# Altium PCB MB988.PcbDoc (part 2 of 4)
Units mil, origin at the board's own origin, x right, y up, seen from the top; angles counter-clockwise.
Board outline 4505 x 6805 mil, 4 copper layers (TopLayer, VCC, GND, BottomLayer), stack 71.6 mil thick; 546 components, 390 nets, 1907 pads, 809 vias.
Unrouted connection lines stored in the file: 2.
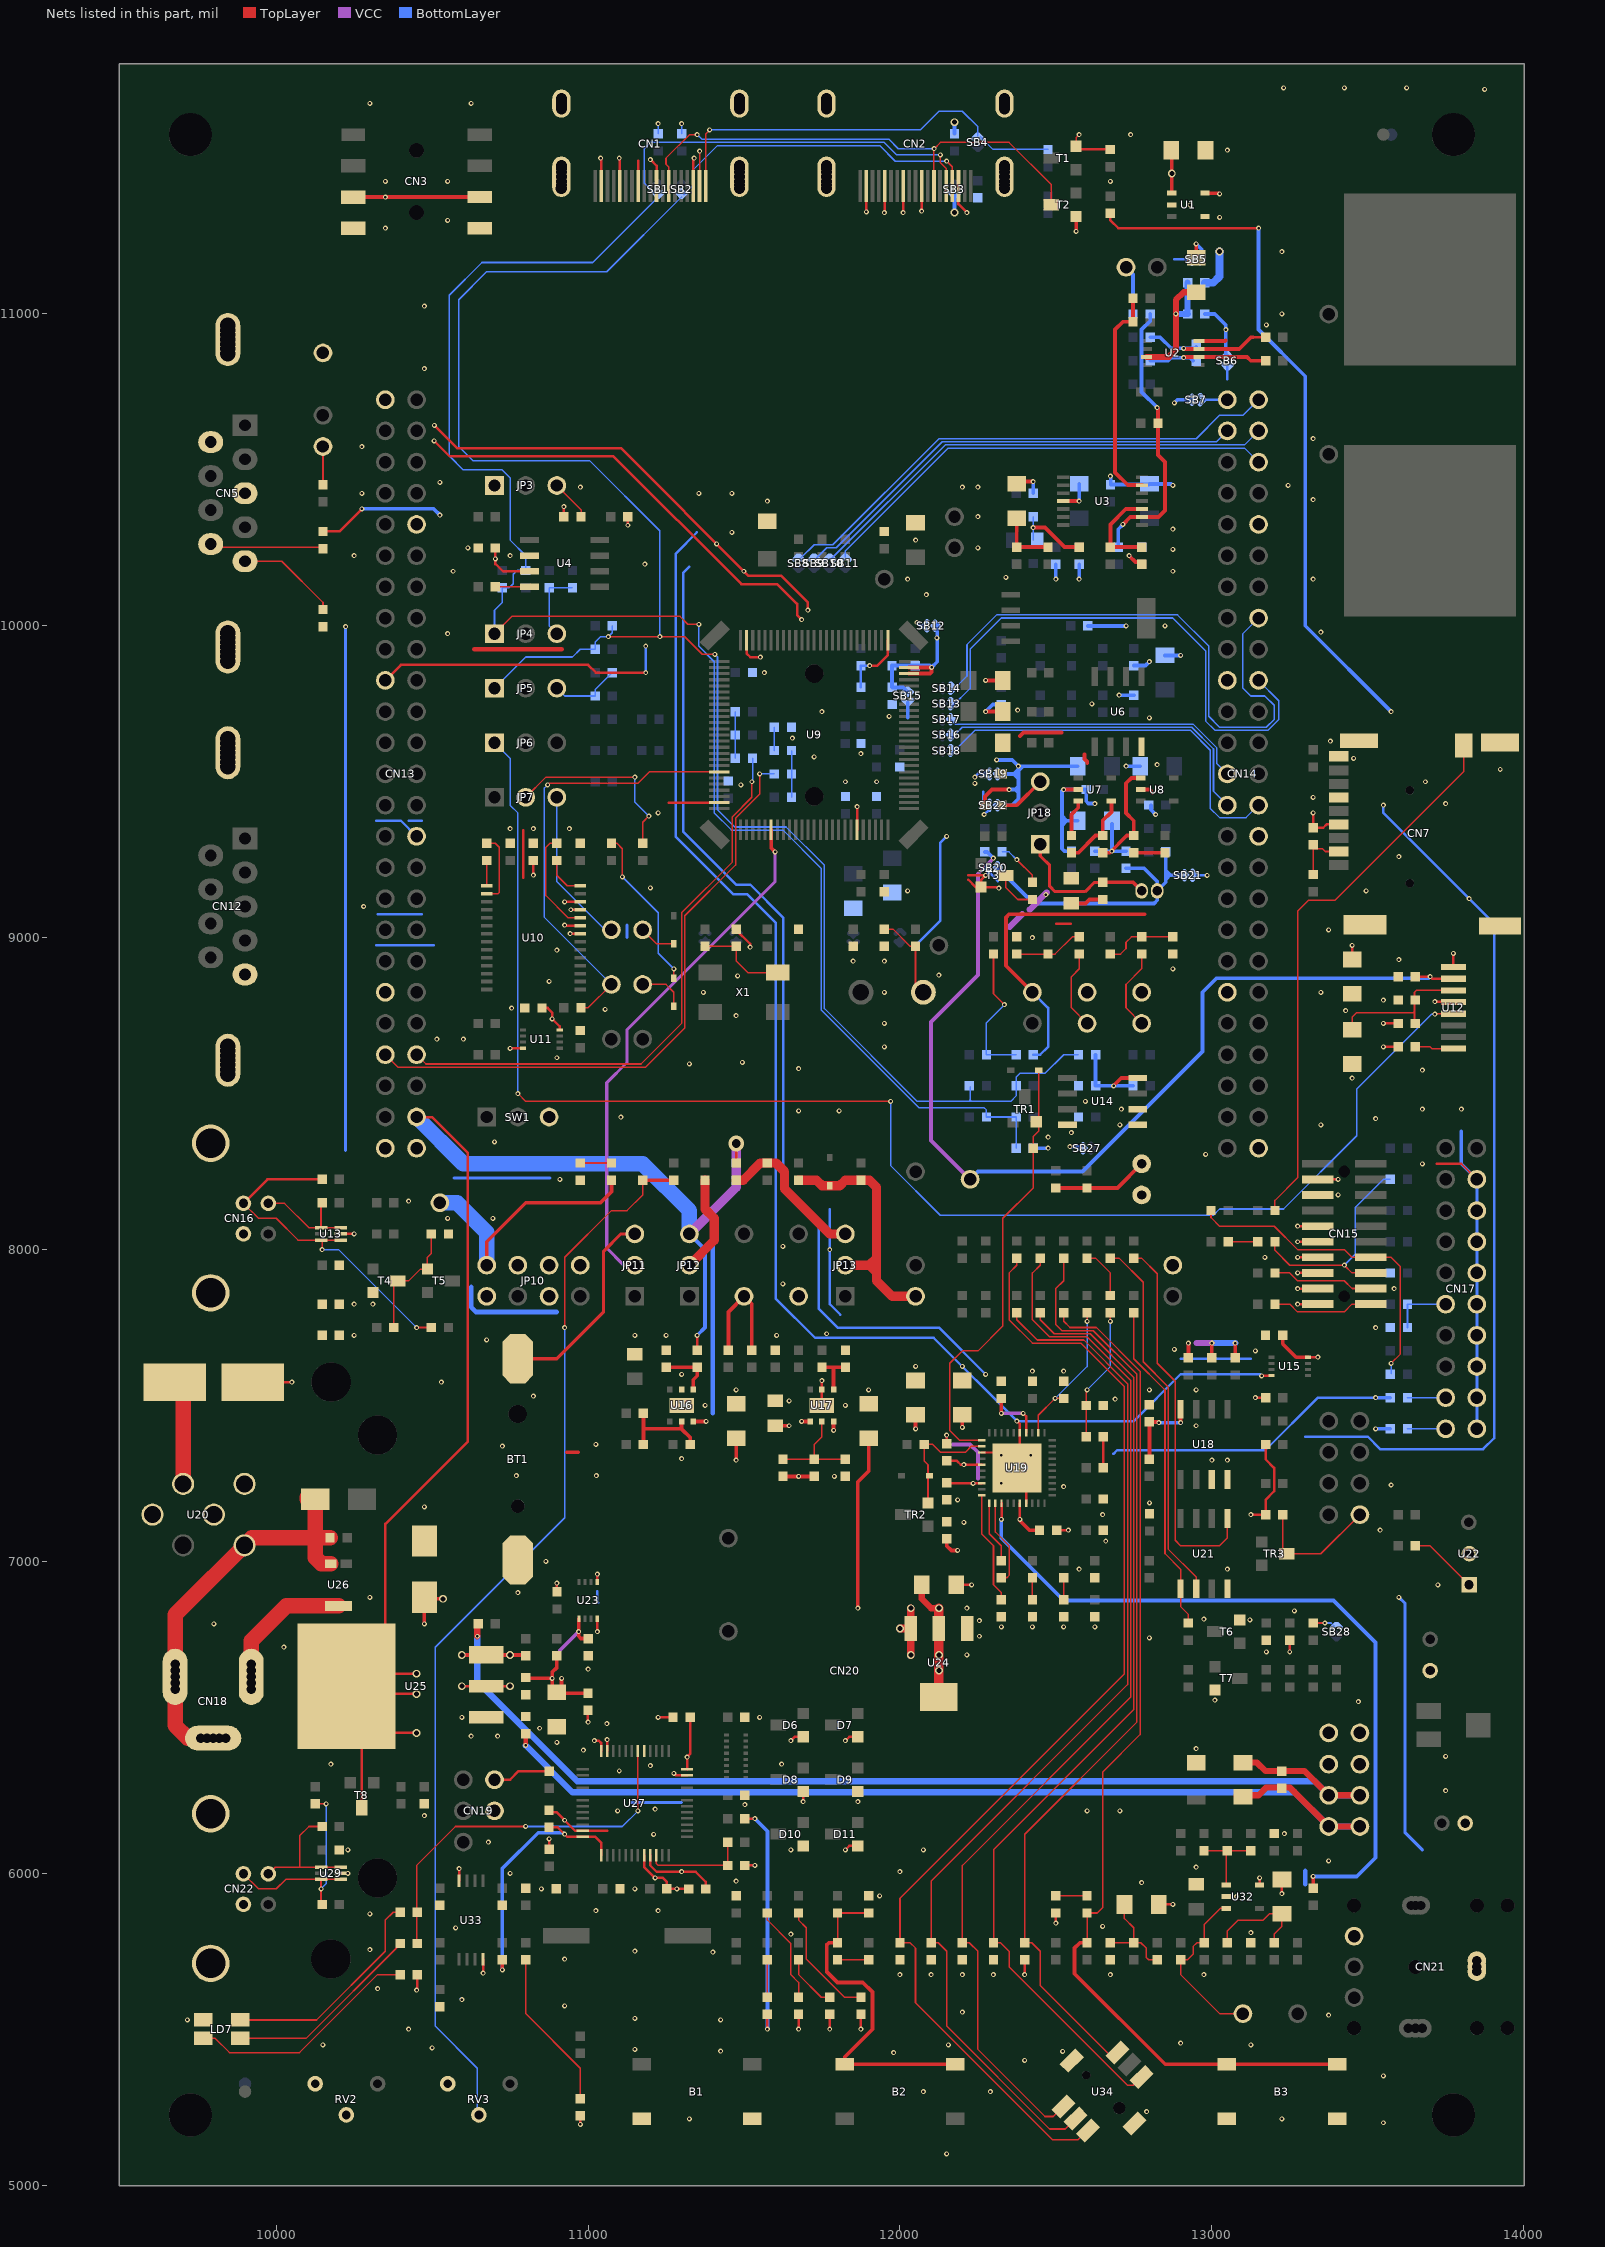
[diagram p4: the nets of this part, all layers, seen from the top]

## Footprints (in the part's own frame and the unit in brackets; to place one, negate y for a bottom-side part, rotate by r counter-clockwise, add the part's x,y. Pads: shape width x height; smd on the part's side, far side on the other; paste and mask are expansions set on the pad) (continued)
XTAL_socket [mil]
  round 80 hole 53 mask+4: 1(100,0) 2(-100,0)
  silkscreen extent -215,-89 214,89

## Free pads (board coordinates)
  round 137.8 hole 137.8 unplated mask+4: 0(9725,5225) 0(13775,5225) 0(13775,11575)
  round 137.79 hole 137.79 unplated mask+4: 0(9725,11575)

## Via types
v1: diameter 16, hole 8, TopLayer to BottomLayer, tented both sides, 786 vias
v2: diameter 25, hole 16, TopLayer to BottomLayer, tented both sides, 20 vias
v3: diameter 50, hole 28, TopLayer to BottomLayer, tented both sides, 3 vias

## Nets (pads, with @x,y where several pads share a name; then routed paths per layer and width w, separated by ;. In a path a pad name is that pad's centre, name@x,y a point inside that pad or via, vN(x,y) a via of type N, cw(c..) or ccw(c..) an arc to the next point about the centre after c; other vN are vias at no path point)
+1V8: C37.1 C41.2 R99.2 R102.2 R114.1 TP12.1 U17.4 | length 548.7
  TopLayer w12: R102.2@11450,7677.5 11450,7800 TP12.1@11500,7850 11525,7825 R99.2@11525,7677.5 ; C37.1@11600,7435 v1(11645,7435) ; C41.2@11625,7272.5 R114.1@11725,7272.5 ; v1(11685,7448.82) U17.4@11712.6,7448.82
  other v1: 11675,7272.5
+2V5: C32.1 C43.1 C49.1 C130.1 C132.1 R166.1 TP13.1 U19.13 U19.16 U19.34 U24.2 | length 3218.7
  TopLayer w8: v1@12325.79,7135.79 U19.13@12325.79,7187.01 ; v1@12384.84,7130.16 U19.16@12384.84,7187.01 ; v1(12395,7475) 12404.53,7465.47 U19.34@12404.53,7412.99
  TopLayer w12: C132.1@12150.28,7072.56 12150.28,7049.72 12165,7035 v1(12185,7035) ; v1(12200,7430) C32.1@12200,7470 ; v1@12325.28,7475.28 C43.1@12325.28,7522.44 ; v1@12384.84,7130.16 12415.28,7099.72 C130.1@12447.56,7099.72 ; R166.1@13325,5952.5 v1(13325,5990)
  TopLayer w20: C49.1@12070,6925 12070,6880 12100,6850 v2(12125,6850)
  TopLayer w30: U24.2@12125,6565 v2(12125,6850)
  VCC w12: v1(12325,7475) v1(12395,7475)
  BottomLayer w12: v1(12325,7135) 12325,7075 12525,6875 13390,6875 13525,6740 13525,6050 13465,5990 v1(13325,5990)
  other v1: 12384.84,7135
  other v2: 12125,6650 12125,6700
+3V3: C6.2 C12.2 C22.1 C23.1 C57.1 C58.1 C60.1 C61.2 C69.2 C76.2 C120.2 C124.2 C133.2 CN7.4 CN13.48 CN19.4 CN20.9 CN20.10 JP12.3 LD1.1 LD2.1 LD3.1 LD4.1 LD6.1 LD10.1 R2.2 R8.2 R9.1 R28.2 R48.1 R49.1 R56.2 R97.2 R110.2 R112.2 R118.2 R133.2 R153.2 R206.1 R237.1 R244.2 T8.3 TP7.1 U4.3 U10.22 U10.26 U11.8 U12.7 U15.8 U23.1 U25.2 U27.1 U27.9 U27.24 U27.36 U27.48 U32.5 U33.8 | length 14599.1
  TopLayer w8: R9.1@10150,10302.5 10202.5,10302.5 v1(10275,10375) ; T8.3@10274.5,6210 U25.2@10274.5,6509.5 ; U25.2@10300,6640 v2@10445,6640 ; U25.2@10305,6450 v2(10450,6450) ; U25.2@10305,6575 v2(10450,6575) ; U25.2@10350,6725 10350,7120 10615,7385 10615,8310 10500,8425 CN13.48@10450,8425 ; v1@10452.5,5627.5 R153.2@10452.5,5675 ; U33.8@10586.61,5975.98 v1(10586.61,6015) ; v2(10595,6600) v2(10750,6600) ; 10702.44,10197.56 C6.2@10702.44,10249.72 ; 10702.44,10200 10727.44,10175 U4.3@10812.5,10175 ; v1(10824.72,9200.28) C12.2@10824.72,9247.56 ; C120.2@10852.44,8774.72 10870.28,8774.72 10885,8760 v1(10885,8740) 10909.06,8715.94 U11.8@10909.06,8704.53 ; C69.2@10874.72,6147.56 10902.44,6147.56 10933.27,6116.73 11023.27,6116.73 11041.73,6098.27 U27.1@11041.73,6057.68 ; R8.2@10922.5,10350 v1(10922.5,10382.5) ; v1(10925,9115) 10925.16,9115.16 U10.26@10974.61,9115.16 ; v1(10942.8,9012.8) U10.22@10974.61,9012.8 ; v1(10975,5195) LD6.1@10975,5222.5 ; v1(11020,6425) 11035,6425 11041.73,6418.27 U27.36@11041.73,6392.32 ; U27.9@11199.21,6057.68 11199.21,6025.79 11220,6005 11345,6005 11377.44,5972.56 C76.2@11377.44,5949.72 ; U27.24@11317.32,6333.27 v1(11317.32,6372.68) 11327.44,6382.79 C61.2@11327.44,6499.72 ; R97.2@11350,7677.5 v1(11350,7725) ; R56.2@11475,8277.5 v3(11475,8340) ; R133.2@11502.5,6175 v1(11535,6175) ; v1(11575,5500) LD4.1@11575,5547.5 ; v1(11675,5500) LD3.1@11675,5547.5 ; v1(11775,5500) LD2.1@11775,5547.5 ; v1(11875,5500) LD1.1@11875,5547.5 ; R2.2@12675,11322.5 12675,11300 12700,11275 v1(13150,11275) ; v1(13125,7150) R112.2@13172.5,7150 13172.5,7197.5 13200,7225 13200,7300 13172.5,7327.5 R110.2@13172.5,7375 ; U32.5@13153.15,5962.4 v1(13153.15,5985) ; v1(13250,6710) R118.2@13250,6747.5 ; U15.8@13309.06,7654.53 13339.53,7654.53 v1(13340,7655) ; v1(13325,9400) R28.2@13325,9352.5 13357.5,9352.5 13367.99,9362.99 CN7.4@13406.65,9362.99 ; C22.1@13450,8930 v1(13450,8975) ; v1(13550,8650) R48.1@13597.5,8650 ; v1(13550,8725) R49.1@13597.5,8725 ; C23.1@13652.56,8875.28 13699.72,8875.28 13706.5,8868.5 U12.7@13775,8868.5
  TopLayer w12: v1(10725,5690) R244.2@10725,5722.5 ; C57.1@10802.28,6625 v1(10885,6625) ; C58.1@10885,6570 10885,6645 10900,6660 R237.1@10900,6697.5 ; C58.1@10912.56,6577.56 C60.1@10999.72,6577.56 ; C58.1@10915,6585 v1(10915,6625) ; U23.1@10970.47,6815.94 10970,6815.47 10970,6760 10977.56,6752.44 C133.2@11000.28,6752.44 ; C124.2@13227.44,7724.72 13227.44,7697.56 13270.47,7654.53 U15.8@13309.06,7654.53
  VCC w12: 10910,6715 v1(10970,6775) ; TP7.1@12225,8225 12100,8350 12100,8730 12250,8880 12250,9205 v1(12300,9255)
  VCC w30: JP12.3@11325,8050 11475,8200 v3(11475,8340)
  BottomLayer w12: v1(10275,10375) 10505,10375 v1(10525,10355) ; v1(10725,5690) 10725,6015 10840,6130 10920,6130 v1(10924.58,6125.42) ; JP12.3@11325,8050 11375,8000 11375,7750 v1(11350,7725) ; v1(11535,6175) 11575,6135 v1(11575,5500) ; TP7.1@12225,8225 12250,8250 12585,8250 12970,8635 12970,8825 13015,8870 13695,8870 v1(13700,8875) ; R206.1@12272.5,9275 12280,9275 v1(12300,9255) ; v1(13150,11275) 13150,10950 13300,10800 13300,10000 v1(13575,9725)
  BottomLayer w50: CN13.48@10450,8425 10600,8275 11175,8275 11325,8125 JP12.3@11325,8050
  other v1: 10450,5625 11300,6005 10985,6395 10702.44,10215
  other v2: 10450,6640
+5V: C39.1 C40.1 C42.1 C48.1 C121.2 C126.1 C127.2 C128.1 CN3.3 JP10.2 JP10.4 JP10.6 JP10.8 L2.2 R53.2 R101.1 R104.2 R105.2 R213.2 R214.2 R221.2 R235.1 R238.1 SB27.2 T2.2 TP8.1 U1.5 U14.8 U16.6 U17.6 U18.8 U19.5 U19.8 U24.3 U25.3 | length 4112.6
  TopLayer w8: C128.1@12149.72,7252.44 12151.37,7250.79 U19.8@12262.01,7250.79 ; C126.1@12150.28,7322.56 12182.44,7322.56 12195,7310 12235,7310 12235.16,7309.84 U19.5@12262.01,7309.84
  TopLayer w12: CN3.3@10247.5,11375 CN3.3@10652.5,11375 ; v1(10475,6800) C48.1@10475,6885 ; C48.1@10480,6880 v2(10535,6880) ; v2(10595,6700) U25.3@10655,6700 ; JP10.2@10675,7950 10675,8025 10800,8150 11040,8150 11075,8185 R53.2@11075,8222.5 ; U25.3@10700,6700 R238.1@10797.5,6700 ; U16.6@11337.4,7448.82 v1(11378.82,7448.82) ; v1(11475,7325) C40.1@11475,7395 ; v1(11787.4,7420) U17.6@11787.4,7448.82 ; v1(11865,6850) 11865,7254.95 11900,7289.95 C42.1@11900,7395 ; v1(12050,7425) C39.1@12050,7470 ; v1(12565,11265) T2.2@12565,11312.5 ; v1(12685,8525) 12710,8550 U14.8@12762.5,8550 ; R235.1@12800,7327.5 12800,7447.28 12827.72,7447.28 v1(12830,7445) ; v1(12900,7445) U18.8@12900,7487.5 ; R101.1@12925,7652.5 v1(12925,7700) ; U1.5@12978.15,11387.4 13022.6,11387.4 v1(13025,11385) ; R104.2@13000,7652.5 v1(13000,7700) ; R105.2@13075,7652.5 v1(13075,7700)
  TopLayer w25: v2(12000,6785) U24.3@12034.45,6785 ; v2(12035,6700) 12034.45,6700.55 12034.45,6849.45 v2(12035,6850)
  VCC w12: 12170,7375 12225,7375 12250,7350 12250,7265
  VCC w20: 12952,7700 v1(13000,7700)
  BottomLayer w12: R221.2@12425,8325 v1(12475,8325) ; v1(12545,8330) SB27.2@12582,8330 ; R213.2@12627.44,8624.94 C121.2@12627.44,8525.28 12627.72,8525 R214.2@12747.5,8525 ; v1(12830,7445) v1(12900,7445) ; 13025,11152.5 v2(13025,11200)
  BottomLayer w20: v1(13000,7700) v1(13075,7700)
  BottomLayer w25: L2.2@12977.5,11100 13005,11100 13025,11120 v2(13025,11200)
  BottomLayer w50: TP8.1@10525,8150 10580,8150 10675,8055 JP10.2@10675,7950
  other v1: 12235,7250 12205,7310 10350,11375
  other v2: 10750,6700
AGND: C3.2 C4.1 C5.2 C8.2 C9.2 C10.2 C11.2 C17.1 C90.1 C92.1 C93.1 C94.2 C95.2 C97.1 C100.1 C102.1 C103.1 C105.1 C106.2 C107.1 C108.2 C109.2 C111.1 C113.1 C114.2 C118.1 CN6.2 CN9.1 L3.2 R15.1 R30.1 R121.2 R188.1 R197.1 R198.2 R207.2 R208.1 SB5.2 SB6.2 SB7.2 SB12.2 SB15.2 SB19.2 SB20.2 SB21.2 SB22.2 U2.4 U3.11 U6.4 U7.2 U8.2 U9.48 U9.49 | length 5627.2
  TopLayer w8: CN6.2@12825,9150 CN6.2@12825,9171.5
  TopLayer w12: U9.48@12029.13,9846.85 12096.85,9846.85 12101.53,9851.53 v1(12101.53,9866.53) U9.49@12029.13,9866.53 ; R121.2@12272.5,9425 12272.5,9452.5 12295,9475 v1(12350,9475) ; v1(12275,9725) C10.2@12330,9725 ; v1(12275,9825) C9.2@12330,9825 ; 12350,9075 12340,9065 12340,8910 CN9.1@12425,8825 ; 12354,9075 12784,9075 ; 12385,9646.5 12396.5,9658 12518.69,9658 ; C5.2@12387.5,10462.5 v1(12427.5,10462.5) ; U3.11@12524.02,10400 v1(12575,10400) ; v1(12525,9475) U7.2@12571.85,9475 ; 12591.96,9588.34 12591.96,9573.04 12600.35,9564.65 12600.35,9560 ; v1(12735,10225) 12755,10205 R15.1@12775,10205 ; U8.2@12771.85,9475 12800,9475 12810,9465 ; C3.2@12950,11180 v1(12950,11225) ; U2.4@12959.69,10913.39 13043.39,10913.39 13045,10915
  VCC w20: 12352,9035 12392,9075 ; 12416,9090 v1@12471,9145
  BottomLayer w8: CN9.1@12425,8825 12475,8775 12475,8650 12450,8625 C118.1@12427.5,8625
  BottomLayer w12: L3.2@11974.72,9802.78 C102.1@11974.72,9872.44 12095.63,9872.44 v1(12101.53,9866.53) 12120,9885 SB12.2@12120,10005 ; L3.2@11975,9802.5 12010.5,9802.5 SB15.2@12025,9788 ; v1(12275,9725) 12297.5,9747.5 R197.1@12325,9747.5 ; v1(12310,9570) 12360,9570 v1(12380,9550) ; SB20.2@12313,9225 12428,9110 12815,9110 12825,9120 12825,9180 12782.56,9222.44 C113.1@12724.72,9222.44 ; SB19.2@12313,9525 12376.5,9525 ; SB22.2@12318,9425 12360,9425 12380,9445 v1(12380,9550) ; v1(12350,9475) 12380,9475 ; 12380,9465 12370,9475 12380,9485 ; 12380,9510 12365,9525 12380,9540 ; 12380,9535 12395,9550 ; C92.1@12427.5,10425 v1(12427.5,10462.5) ; v1(12500,10150) R188.1@12500,10197.5 ; 12520,9360 12535,9375 12520,9390 ; 12520,9375 C114.2@12570,9375 ; R207.2@12550,9277.5 12527.5,9277.5 12520,9285 12520,9470 v1(12525,9475) C107.1@12597.15,9475 ; C108.2@12570,9550 v1(12380,9550) ; C97.1@12574.72,10197.44 12574.72,10150.28 v1(12575,10150) ; v1(12575,10400) C94.2@12575,10455 ; C107.1@12597.44,9475.28 12597.44,9437.56 12605,9430 v1(12625,9430) ; C100.1@12602.56,9999.72 12724.72,9999.72 v1(12725,10000) ; v1(12675,10480) 12675.87,10479.13 12675.87,10453.15 C95.2@12798.15,10453.15 ; v1(12702.56,9777.56) C105.1@12750.28,9777.56 ; v1(12725,9550) C109.2@12770,9550 ; R198.2@12750,9872.5 12787.5,9872.5 v1(12800,9885) ; C95.2@12800,10455 12870,10455 v1(12875,10450) ; C111.1@12805,9425 12805,9410 v1(12820,9395) ; CN6.2@12825,9150 12852.5,9177.5 R208.1@12852.5,9275 ; C106.2@12850,9905 v1(12900,9905) ; 12852.5,9190 12855,9190 12865,9200 12865,9202.5 12852.5,9215 ; 12852.5,9200 SB21.2@12907,9200 ; v1(12880,10715) 12890,10725 SB7.2@12937,10725 ; v1(12950,11225) 12968,11207 SB5.2@12968,11182 ; C90.1@12977.56,10999.72 13009.72,10999.72 13045,10964.43 SB6.2@13045,10868 ; SB6.2@13050,10863 SB6.2@13050,10868
  other v1: 12467.79,9138.32 12825,9555 12800,9705 12377.5,9730 12615.31,9750 12118.17,9961.35 13350,9980 12850,10000 12085,10100 12025,10150 13325,10150 12340,10155 12875,10175 12875,10245 12250,10250 12050,10275 12875,10310 12250,10350 13325,10405 12200,10445 12250,10445 13325,10600 13045,10950 13175,10965 13225,11200 13875,11720 13230,11725 13425,11725 13625,11725
AIN_1: R134.2 R138.1 U27.10 | length 332.7
  TopLayer w5: U27.10@11218.9,6057.68 11218.9,6031.1 11225,6025 R138.1@11447.5,6025 R134.2@11447.5,6100
BOOT0: JP9.2 R216.1 U9.94 | length 1430
  TopLayer w5: v1(10870,9490) 10875,9495 11160,9495 11196.89,9531.89 U9.94@11420.87,9531.89 ; R216.1@10977.5,8775 11000,8775 JP9.2@11075,8850
  BottomLayer w5: v1(10870,9490) 10860,9480 10860,9065 JP9.2@11075,8850
D5V: CN13.49 CN14.19 JP10.1
E5V: C34.1 JP10.5 U20.3 | length 313.1
  TopLayer w50: U20.3@9701.57,7248.43 C34.1@9701.57,7561.57
GND: B1.1 B1.4 B3.1 B3.4 BT1.2 C1.2 C6.1 C7.1 C12.1 C15.2 C16.2 C18.2 C19.2 C20.1 C21.1 C22.2 C23.2 C24.2 C25.2 C26.1 C27.2 C28.2 C29.1 C30.2 C31.2 C32.2 C34.2 C36.2 C37.2 C38.2 C39.2 C40.2 C42.2 C43.2 C44.2 C45.1 C46.1 C48.2 C49.2 C51.1 C52.2 C53.1 C54.2 C57.2 C58.2 C59.2 C60.2 C61.1 C62.1 C63.1 C69.1 C71.2 C73.1 C74.1 C76.1 C77.1 C79.2 C80.2 C81.2 C82.2 C84.1 C85.1 C86.1 C87.1 C88.1 C99.2 C110.1 C112.2 C115.2 C116.2 C117.2 C119.1 C120.1 C121.1 C122.2 C123.1 C124.1 C125.1 C126.2 C127.1 C128.2 C129.2 C130.2 C131.2 C132.2 C133.1 C134.2 C135.2 CN1.0 CN1.2 CN1.5 CN1.8 CN1.11 CN1.17 CN2.0 CN2.2 CN2.5 CN2.8 CN2.11 CN2.17 CN3.4 CN5.0 CN5.3 CN5.6 CN7.0 CN7.6 CN7.9 CN10.1 CN11.1 CN12.0 CN12.5 CN13.1 CN13.10 CN13.19 CN13.30 CN13.39 CN13.50 CN14.1 CN14.10 CN14.30 CN14.39 CN14.50 CN15.3 CN15.5 CN15.9 CN15.11 CN15.13 CN15.15 CN15.17 CN15.19 CN16.4 CN17.4 CN17.6 CN17.8 CN17.10 CN17.12 CN17.14 CN17.16 CN17.18 CN17.20 CN19.2 CN20.11 CN20.12 CN21.1 CN21.4 CN22.0 CN22.4 D6.2 D7.2 D8.2 D9.2 D10.2 D11.2 JP3.1 JP14.2 L3.1 L5.1 LD7.1 LD8.2 R19.1 R63.1 R66.2 R76.1 R103.1 R111.2 R115.1 R116.1 R126.2 R127.1 R132.2 R137.1 R138.2 R144.2 R145.1 R151.2 R152.1 R160.1 R168.2 R175.1 R182.2 R219.1 R226.1 R229.1 R232.1 R233.2 R234.1 R242.2 R243.2 RV2.2 RV2.3 RV3.3 SB5.1 SB6.1 SB7.1 SB12.1 SB15.1 SB19.1 SB20.1 SB21.1 SB22.1 SW1.3 T3.1 T4.1 T6.1 T7.1 TP2.1 U1.2 U1.4 U4.2 U9.20 U9.74 U9.99 U10.23 U10.25 U11.4 U12.5 U12.8 U13.2 U14.4 U14.5 U14.6 U15.4 U16.0 U16.2 U17.0 U17.2 U18.3 U18.4 U19.0 U19.3 U19.17 U19.35 U20.4 U20.5 U20.6 U21.4 U22.2 U23.4 U23.5 U24.1 U25.1 U27.8 U27.23 U27.35 U27.47 U28.1 U29.2 U32.2 U33.4 U34.0 | length 27129.4
  TopLayer w8: C34.2@9925,7575 v1(10050,7575) ; U29.2@10206.3,6000 v1(10230,6000) ; U13.2@10206.3,8050 v1(10250,8050) ; v1@10229.72,6074.72 v1(10230,6075) ; CN13.19@10350,9825 10400,9875 11000,9875 11025,9850 v1(11185,9850) ; v1(10506.71,10593.29) 10556.5,10543.5 11081.5,10543.5 11491.5,10133.5 11606.5,10133.5 11670,10070 11670,10035 v1(11685,10020) ; v1(10507.29,10642.71) 10580,10570 11105,10570 11515,10160 11620,10160 11705,10075 v1(11705,10050) ; v1(10550,8100) v1@10552.5,8097.5 ; v1(10663.39,5680) U33.4@10663.39,5724.02 ; CN19.2@10700,6300 10750,6300 10777.5,6327.5 R127.1@10875,6327.5 ; v1(10750,8645) 10750.47,8645.47 U11.4@10790.94,8645.47 ; v1(10750,9350) v1@10750.28,9349.72 ; v1(10755,8774.5) v1@10755.22,8774.72 ; 10792.78,9192.78 10792.78,9344.94 ; v1@10824.72,9349.72 v1(10825,9350) ; C69.1@10870,6195 10900,6195 10958.58,6136.42 U27.47@10982.68,6136.42 11061.42,6136.42 ; R137.1@10875,6077.5 v1(10875,6110) ; v1(10900,6930) 10900.28,6929.72 C131.2@10900.28,6902.44 ; v1(10925,9040) 10926.61,9038.39 U10.23@10974.61,9038.39 ; v1(10945,9089.57) U10.25@10974.61,9089.57 ; C60.2@10999.72,6522.56 10999.72,6485.28 v1(11000,6485) ; v1(11000,6654.94) v1@11000.28,6655.22 ; v1@11029.53,6775.47 v1(11030,6775) 11030,6815.47 U23.4@11029.53,6815.94 ; U23.5@11029.53,6934.06 v1(11029.53,6959.53) ; v1(11040,11500) 11042.52,11497.48 CN1.2@11042.52,11410 ; U27.35@11061.42,6392.32 v1(11061.42,6428.58) ; v1(11100,11500) 11101.57,11498.43 CN1.5@11101.57,11410 ; v1(11127.5,10322.5) R182.2@11127.5,10350 ; CN1.8@11160.63,11410 11160.63,11490.63 ; U27.8@11179.53,6057.68 11179.53,6020.47 v1(11215,5985) 11240,5985 11252.5,5972.5 C74.1@11252.5,5950 C76.1@11322.15,5950 ; v1(11200,11495) 11219.68,11475.32 CN1.11@11219.68,11410 ; v1(11225,6500) 11225.28,6499.72 C61.1@11272.44,6499.72 ; v1(11250,7725) v1@11250.28,7724.72 ; 11258.47,9433.47 U9.99@11420.87,9433.47 ; v1(11275,6320) 11281.42,6313.58 U27.23@11317.32,6313.58 ; CN1.17@11337.8,11410 11337.8,11497.8 v1(11340,11500) ; v1(11412.47,10262.47) v1(11412.47,10262.47) ; v1@11474.72,5974.72 v1(11475,5975) ; C24.2@11475,9025 11520,8980 v1(11520,8970) ; R138.2@11502.5,6025 v1(11535,6025) ; U9.74@11508.46,9954.13 11508.46,9911.54 11520,9900 v1(11552.44,9900) ; v1(11650,6425) 11662.5,6437.5 D6.2@11690,6437.5 ; v1(11690,6230) D8.2@11690,6262.5 ; U17.0@11750,7500 v1(11750,7580) ; v1(11825,6075) 11837.5,6087.5 D11.2@11865,6087.5 ; v1(11825,6425) 11837.5,6437.5 D7.2@11865,6437.5 ; U9.20@11862.79,9345.87 v1(11862.8,9420) ; v1(11892.52,11327.52) CN2.2@11892.52,11410 ; v1(11950,11325) 11951.57,11326.57 CN2.5@11951.57,11410 ; v1(12000,5675) v1@12000.28,5675.28 ; v1(12010,11325) 12010.63,11325.63 CN2.8@12010.63,11410 ; v1@12022.44,9147.44 v1(12025,9150) ; v1(12069.68,11329.68) CN2.11@12069.68,11410 ; C126.2@12150,7375 v1(12150,7405) ; C49.2@12185,6925 v1(12230,6925) ; CN2.17@12187.8,11410 12187.8,11352.2 v1(12215,11325) ; v1(12200,5675) v1@12200.28,5675.28 ; v1(12215,6700) v1@12215.55,6700.55 ; v1(12215,6850) v1@12215.55,6849.45 ; 12219.5,9185.86 12242.86,9162.5 12254,9162.5 12314.05,9162.5 v1(12317.55,9159) ; 12219.5,9200 v1(12275,9200) 12260,9185 T3.1@12260,9162.5 ; U19.3@12262.01,7349.21 U19.0@12309.21,7349.21 ; v1(12300,5675) v1@12300.28,5675.28 ; v1(12375,7450) 12384.84,7440.16 12384.84,7355.16 U19.0@12385,7355 ; v1(12400,5675) 12400.28,5675.28 C88.1@12400.28,5722.44 ; U19.17@12404.53,7187.01 12404.53,7244.53 U19.0@12405,7245 ; v1(12500,5840) R152.1@12500,5872.5 ; 12501.97,9045 12548.03,9045 ; C130.2@12502.56,7099.72 12539.72,7099.72 v1(12540,7100) ; C127.1@12799.72,7502.56 C127.1@12800,7502.85 ; C80.2@12830,5900 v1(12875,5900) ; v1(13140,7525) 13140.28,7524.72 C125.1@13172.56,7524.72 ; v1@13160.47,7595.47 U15.4@13190.94,7595.47 ; v1(13225,5935) C82.2@13225,5980 ; v1(13275,7825) CN15.19@13340,7825 ; v1(13275,7875) CN15.17@13340,7875 ; v1(13275,7925) CN15.15@13340,7925 ; v1(13275,7975) CN15.13@13340,7975 ; v1(13275,8025) CN15.11@13340,8025 ; v1(13275,8075) CN15.9@13340,8075 ; CN15.3@13340,8225 v1(13405,8225) ; v1(13550,8800) v1@13550.28,8800.28 ; v1(13715,8795) U12.5@13773.7,8795 ; 13721.61,8275 13800,8275 CN17.4@13850,8225 ; U12.8@13775,8905.91 v1(13775,8950)
  TopLayer w12: 10932.53,7350 10967.47,7350
  TopLayer w15: 10635,9925 10916.01,9925
  BottomLayer w8: 10321.61,8975 10505,8975 ; 10321.61,9375 10400,9375 CN13.30@10450,9325 ; 10325,9075 10466.01,9075 ; 10425,9375 10466.01,9375 ; v1@10592.5,5597.5 v1(10595,5595) ; 11030.16,6904.84 11030.16,6869.33 11031.96,6867.53 ; v1(11185,9850) v1(11185,9935) ; 11304.5,10107 11304.5,10169.14 11325,10189.64 ; 11304.5,10154.5 11304.5,9340.5 11475,9170 11520,9170 11626.5,9063.5 11626.5,8198.5 11740,8085 11740,7810 11800,7750 12125,7750 v1(12275,7600) ; 11349,10300 11281.5,10231.5 11281.5,9323.5 11465,9140 11510,9140 11601.5,9048.5 11601.5,7843.5 11728.5,7716.5 12108.5,7716.5 v1(12375,7450) 12750,7450 12900,7600 13155,7600 v1(13160,7595) ; v1@11564.72,9850.28 v1(11565,9850) ; 11775,8130 11775,7825 11809.02,7790.98 ; v1(11875,9590) v1@11875.28,9590.28 ; 12050,8975 12130,9055 12130,9305 v1(12150,9325) ; v1(12055,10010) v1@12057,10008 ; v1(12240,9515) 12250,9525 SB19.1@12275,9525 ; 12267.68,9467.68 12267.68,9432.32 SB22.1@12275,9425 ; v1(12270,9395) SB22.1@12285,9410 ; v1(12275,9200) 12285,9210 12313.89,9181.11 ; 12684.64,7345 12696.14,7356.5 13171.5,7356.5 13340,7525 v1(13525,7525) ; 12880,11175 SB5.1@12925,11175 ; 12900,7650 13125,7650 ; SB21.1@12950,9200 v1(12985,9200) ; SB7.1@12976,10725 CN14.1@13050,10725 ; 13050,10789.92 SB6.1@13050,10830 ; 13300,7400 13500,7400 13540,7360 13870,7360 13905,7395 13905,9045 13550,9400 v1(13550,9425)
  BottomLayer w10: 10222.5,8317.5 v1(10222.5,9997.5) ; 10570.75,8230 10877.43,8230 ; 11125,9000 11125,9041.01 ; 11135,6227.5 11300,6227.5 ; v1(11621,6350) v1@11621,6351 ; 12025,9704.9 SB15.1@12025,9755 ; v1(12055,10010) 12065,10000 SB12.1@12074,10000 ; v1(13600,6885) 13620,6865 13620,6130 13675,6075 ; 13800,8380 13800,8275 CN17.4@13850,8225 CN17.20@13850,7425
  BottomLayer w12: v1@10249.72,8050.28 v1(10250,8050) ; v1(10600,8675) v1@10600.28,8675.28 ; v1(11825,9500) v1@11825.28,9499.72 ; v1@11924.72,9499.72 v1(11925,9500) ; v1@12539.72,7100.28 v1(12540,7100) ; v1(13525,7425) R234.1@13572.5,7425 ; v1(13525,7525) R232.1@13572.5,7525
  BottomLayer w15: 10625,7880 10625,7815 10640,7800 10900,7800 ; 11390,8025.31 11400,8015.31 11400,7475 ; 13300,5965 13300,6007.47
  other v1: 12150,5100 13550,5200 11325,5212.5 13225,5212.5 12790.86,5235.8 12075,5300 12290,5300 13550,5350 12400,5400 11980,5425 12521.44,5428.56 11425,5430 11150,5435 10500,5440 10150,5450 12155,5450 13125,5450 12900,5455 10425,5500 9715,5529.53 11425,5530 11150,5535 13375,5545 12200,5555 10925,5575 10325,5630 12100.28,5675.28 12675,5675 12975,5675 10925,5725 11400,5747.5 11150,5750 10300,5755 11650,5805 13125,5810 10575,5825 12650,5830 10300,5870 11025,5880 11225,5880 13080,5925 11935,5927.5 10850,5950 11150,5950 11285,5950 12775,5970 10750,6000 12000,6005 12950,6020 13375,6040 11650,6075 12075,6075 10680,6100 11210,6125 13232.5,6127.5 10925,6170 10475,6185 11095,6200 12600,6200 12705,6200 11215,6205.79 11502.56,6220 11865,6230 13750,6265 11100,6328.03 11200,6345.14 10175,6350 13750,6375 12950,6400 10900,6420 10625,6440 10710,6440 10845,6465 11060,6480 10595,6500 11550,6500 13470,6550 13010,6555 13175,6710 10025,6725 12800,6755 12255,6760 12325,6790 12425,6790 12525,6790 12625,6790 9800,6800 12255,6810 13122.5,6812.5 12975,6815 13265,6841.5 10300,6885 10775,6900 13725,6925 12575,6975 13050,6975 10865,7000 12660,7065 13540,7100 12205,7125 12650,7150 10475,7175 12800.28,7187.44 12184.72,7197.44 12525,7240 13575,7245 12325,7250 11790,7272.5 10770,7275 11026.96,7275 13000,7325 13050,7325 11300,7329.5 12325,7340 12420,7340 10725,7370 11025,7375 12950,7435 11375,7500 11825,7500 11645,7515 12690,7520 10825,7530 11475,7550 11900,7550 12800,7550 12950,7550 10530,7575 11300,7600 12425,7610 12525,7610 12050,7625 12200,7625 13140,7675 12880,7680 10675,7710 10250,7725 11150,7725 11605,7725 11765,7730 13525,7750 10250,7825 10310,7825 13585,7875 11625,7890 13170,7975 11775,8000 11625,8010 10695,8100 10425,8155 13405,8175 10910,8225 13675,8275 12980,8305 10700,8345 12475,8360.5 12550,8375 12705,8400 13350,8400 13525,8420 11105,8425 11675,8445 11805,8445 12710,8450 13675,8450 13800,8450 12595,8475 13450,8550 13675,8575 11675,8580 11325,8595 11495,8600 10900,8615 11950,8650 10515,8675 11950,8725 11475,8750 13428.8,8766.23 11055,8770 11370,8825 11950,8825 13350,8825 10875,8860 11479.66,8877.92 12125,8880 12875,8900 11850,8925 11950,8925 13600,8930 10900,8960 12425,9000 13375,9025 10280,9100 13825,9125 13495,9150 11200,9160 13600,9260 10940,9350 11225,9400 13750,9430 13325,9450 11490,9490 12240,9495 13685,9500 13925,9540 13455,9575 11725,9580 13380,9630 11655,9640 11965,9710 11750,9725 10550,9975 10567.43,10175 11500,10175 11182.5,10197.5 10250,10225 10750,10225 10615,10249.72 11461,10300 11575,10400 10275,10425 11355,10425 11461,10425 10975,10445 13245,10450 10525,10460 10275,10575 10475,10825 13225,11000 10475,11025 10350,11275 10550,11300 13025,11310 12930,11350 10350,11425 10550,11425 12675,11425 13050,11525 12740,11575 10300,11675 10625,11675
HDMI_5V_SINK: CN1.18 R1.1 R172.2 R173.2 SB3.1 T1.1 | length 386.7
  TopLayer w5: CN1.18@11357.48,11410 v1(11357.48,11522.52) ; T1.1@12565,11537.5 12565,11565 v1(12575,11575)
  TopLayer w8: T1.1@12562.5,11527.5 R1.1@12675,11527.5
  BottomLayer w5: R173.2@11225,11577.5 v1(11225,11610) ; R172.2@11300,11577.5 v1(11300,11610)
  BottomLayer w12: v2(12175,11325) SB3.1@12175,11380
HDMI_5V_SOURCE: C1.1 R174.1 U1.1 | length 173.2
  TopLayer w12: U1.1@12871.85,11387.4 C1.1@12871.85,11523.15
  BottomLayer w12: R174.1@12175,11577.5 v2(12175,11615)
  other v2: 12871.85,11450
IRDA_RXD: JP6.1 U12.4 | length 4791.9
  TopLayer w5: v1(10775,8500) 10800,8475 v1(11970,8475) ; v1@13716.3,8756.3 U12.4@13775,8756.3
  BottomLayer w5: JP6.1@10700,9625 10750,9575 10750,9425 10775,9400 v1(10775,8500) ; v1(11970,8475) 11970,8269.14 12129.14,8110 13005,8110 13025,8130 13230,8130 13465,8365 13465,8515 13705,8755 v1(13715,8755)
LED_STLINK: R143.1 R149.1 U27.30 | length 1224.7
  TopLayer w5: R149.1@10450,5777.5 10450,6025 10575,6150 v1(10800,6150) ; R143.1@10452.5,5872.5 R143.1@10452.5,5875 ; v1@11159.84,6200.16 U27.30@11159.84,6392.32
  BottomLayer w5: v1(10800,6150) 11110,6150 v1(11160,6200)
MCO: U27.29
NetB3_2: B3.2 B3.3 C78.2 R90.1 R167.1 | length 3359.3
  TopLayer w5: R90.1@12527.5,7797.5 R90.1@12525,7797.5 12525,7770 12545,7750 12630,7750 12770,7610 12770,6445 12650,6325 12650,5890 12632.56,5872.56 C78.2@12599.72,5872.56 C78.2@12600,5872.28 ; R167.1@12600,5777.5 C78.2@12600,5872.28 ; C78.2@12602.72,5875 C78.2@12600,5872.28
  TopLayer w12: R167.1@12600,5777.5 12577.5,5777.5 12560,5760 12560,5678 12850.5,5387.5 B3.3@13402.17,5387.5
NetBT1_1: BT1.1 JP11.3 | length 654.9
  TopLayer w10: BT1.1@10775,7650 10900,7650 11050,7800 11050,7995 11105,8050 JP11.3@11150,8050
NetC2_2: C2.2 R3.1 U3.6 | length 694.1
  TopLayer w12: C2.2@12747.5,10985 R3.1@12747.5,11050 ; C2.2@12747.56,10975.28 12715.28,10975.28 12690,10950 12690,10491.66 12730.48,10451.18 U3.6@12775.98,10451.18
NetC13_1: C13.1 U10.24 | length 333.9
  TopLayer w5: C13.1@10899.72,9302.56 10877.56,9302.56 10865,9290 10865,9135 10936.02,9063.98 U10.24@10974.61,9063.98
NetC13_2: C13.2 U10.28 | length 136.2
  TopLayer w5: C13.2@10899.72,9247.56 10899.72,9200.28 10933.66,9166.34 U10.28@10974.61,9166.34
NetC14_1: C14.1 U10.1 | length 81
  TopLayer w5: U10.1@10675.39,9166.34 C14.1@10675.39,9247.33
NetC14_2: C14.2 U10.2 | length 231.2
  TopLayer w5: C14.2@10675.28,9302.44 10702.56,9302.44 10715,9290 10715,9145 10710.75,9140.75 U10.2@10675.39,9140.75
NetC19_1: C19.1 R38.2 X2.1 | length 280.6
  TopLayer w5: C19.1@11950,9027.5 11977.5,9027.5 12032.5,8972.5 R38.2@12050,8972.5 12050,8850 X2.1@12075,8825
NetC21_2: C21.2 R40.2 R42.1 | length 222.8
  TopLayer w5: C21.2@12375,8947.5 12497.5,8947.5 12552.5,9002.5 R42.1@12575,9002.5
NetC24_1: C24.1 R36.1 X1.1 | length 296.1
  TopLayer w5: R36.1@11375,8972.5 C24.1@11475,8972.5 11475,8925 11512.01,8887.99 X1.1@11608.27,8887.99
NetC26_2: C26.2 R43.2 R45.1 | length 234.5
  TopLayer w5: R43.2@12675,8947.5 12707.5,8947.5 12725,8965 12725,8985 12742.5,9002.5 C26.2@12875,9002.5
NetC29_2: C29.2 CN16.0 R76.2 | length 50.9
  TopLayer w5: CN16.0@9790,7861 CN16.0@9826,7825
NetC33_2: C33.2 R94.1 R233.1 | length 429.6
  TopLayer w5: C33.2@12597.5,7400 12597.5,7547.5 v1(12600,7550) ; v1(12675,7770) R94.1@12675,7797.5
  BottomLayer w5: v1(12600,7550) 12675,7625 v1(12675,7770)
NetC50_1: C50.1 U19.12 | length 278.3
  TopLayer w5: U19.12@12306.1,7187.01 12306.1,7093.9 12350,7050 12350,6955 12342.5,6947.5 C50.1@12325,6947.5
NetC50_2: C50.2 U19.11 | length 200.5
  TopLayer w5: U19.11@12286.42,7187.01 12286.42,7088.58 12325,7050 C50.2@12325,7002.5
NetC52_1: C52.1 U19.10 | length 360
  TopLayer w5: U19.10@12262.01,7211.42 12262.01,7087.99 12300,7050 12300,6925 12325,6900 C52.1@12325,6877.5
NetC72_2: C72.2 R141.1 R241.2 U32.1 | length 261.4
  TopLayer w5: R141.1@12975,6072.5 R241.2@13125,6072.5 ; U32.1@13046.85,5962.4 13046.85,6069.35 C72.2@13050,6072.5
NetC78_1: C78.1 R152.2 | length 99.7
  TopLayer w5: R152.2@12500.06,5927.56 C78.1@12599.72,5927.56
NetC80_1: C80.1 R168.1 R169.2 R171.1 | length 325.3
  TopLayer w5: R168.1@12675,5777.5 12772.5,5777.5 12790,5760 12790,5730 12797.5,5722.5 R171.1@12825,5722.5 ; C80.1@12720,5900 12720,5855 12750,5825 R169.2@12750,5777.5
NetC82_1: C82.1 R164.2 R245.1 | length 338.1
  TopLayer w5: R164.2@13050,5777.5 13050,5815 13085,5850 13165,5850 13185,5870 C82.1@13225,5870 13225,5830 13200,5805 R245.1@13200,5777.5
NetC83_1: C83.1 R158.2 | length 100
  TopLayer w5: C83.1@11800,5722.5 R158.2@11900,5722.5
NetC83_2: B2.2 B2.3 C83.2 R150.1 R151.1 | length 1103
  TopLayer w5: C83.2@11800,5777.5 R150.1@11800,5872.5 R151.1@11900,5872.5
  TopLayer w12: C83.2@11800,5777.5 11772.5,5777.5 11765,5770 11765,5685 11800,5650 11881,5650 11912,5619 11912,5500 11822.83,5410.84 B2.2@11822.83,5387.5 ; B2.2@11835,5387.5 B2.3@12177.17,5387.5
NetC89_2: C89.2 R170.2 TP15.1 U32.3 | length 563
  TopLayer w5: U32.3@13046.85,5887.6 13027.6,5887.6 12975.28,5835.28 C89.2@12975.28,5777.44 12952.44,5777.44 12940,5765 12940,5740 12922.5,5722.5 R170.2@12900,5722.5 12900,5675 13025,5550 TP15.1@13100,5550
NetC90_2: C3.1 C90.2 L2.1 U2.7 | length 477.5
  TopLayer w20: U2.7@12790.31,10862.2 12862.2,10862.2 12885,10885 12885,11045 12910,11070 C3.1@12950,11070
  BottomLayer w20: v1(12885,11000) 12885.28,10999.72 C90.2@12922.56,10999.72 12922.5,10999.78 L2.1@12922.5,11100
NetC118_2: C118.2 R39.2 R212.1 | length 455.8
  TopLayer w5: R39.2@12300,8947.5 12300,8820 v1(12335,8785)
  BottomLayer w5: v1(12335,8785) 12277.5,8727.5 R212.1@12277.5,8625 C118.2@12372.5,8625
NetCN1_13: CN1.13 CN2.13 T2.3 | length 1637.2
  TopLayer w5: CN1.13@11259.06,11410 11259.06,11470.94 11250,11480 11250,11500 11325,11575 v1(11350,11575) ; CN2.13@12109.06,11400 v1@12109.06,11530 ; v1(12110,11530) 12130,11550 12350,11550 12485,11415 T2.3@12485,11350.5
  BottomLayer w5: v1(11350,11575) 11365,11560 11965,11560 11995,11530 v1(12110,11530)
NetCN6_1: CN6.1 JP18.1 R25.1 | length 468.4
  TopLayer w10: 12450,9262.5 JP18.1@12450,9300 ; 12453.57,9258.93 12480,9232.5 12480,9165 12497.5,9147.5 12593.82,9147.5 12623.82,9177.5 R25.1@12650,9177.5
  TopLayer w12: R25.1@12650,9177.5 12747.5,9177.5 CN6.1@12775,9150
NetCN7_10: CN7.10 R64.1 | length 1792.6
  TopLayer w5: R64.1@13202.5,8125 13202.5,8157.5 13275,8230 13275,9085 13310,9120 13395,9120 13808.23,9533.23 CN7.10@13808.23,9616.93
NetCN13_43: CN13.43 R95.2 | length 1990.3
  TopLayer w5: CN13.43@10350,8625 10390,8585 11185,8585 11310,8710 11310,9070 11472.93,9232.93 11472.93,9382.93 11550,9460 v1(11550,9525)
  BottomLayer w5: v1(11550,9525) R95.2@11597.5,9525
NetCN13_44: CN13.44 R93.2 | length 1860.5
  TopLayer w5: CN13.44@10450,8625 10480,8595 11170,8595 11300,8725 11300,9080 11462.93,9242.93 11462.93,9387.93 11525,9450 v1(11525,9500)
  BottomLayer w5: v1(11525,9500) 11527.5,9502.5 R93.2@11527.5,9575
NetCN14_2: CN14.2 SB8.1 | length 1677
  BottomLayer w5: SB8.1@11683,10218 11725,10260 11785,10260 12125,10600 12950,10600 13025,10675 13100,10675 CN14.2@13150,10725
NetCN14_3: CN14.3 SB9.1 | length 1485.6
  BottomLayer w5: SB9.1@11733,10218 11765,10250 11795.86,10250 12135.86,10590 13015,10590 CN14.3@13050,10625
NetCN14_4: CN14.4 SB10.1 | length 1535.6
  BottomLayer w5: SB10.1@11783,10218 12145,10580 13105,10580 CN14.4@13150,10625
NetCN14_6: CN14.6 SB11.1 | length 1500.3
  BottomLayer w5: SB11.1@11825,10220 11825,10240 12155,10570 13105,10570 CN14.6@13150,10525
NetCN14_16: CN14.16 SB14.1 | length 1896.6
  BottomLayer w5: SB14.1@12168,9792 12215,9839 12215,9940 12310,10035 12890,10035 12990,9935 12990,9710 13025,9675 13175,9675 13200,9700 13200,9745 13170,9775 13125,9775 13100,9800 13100,9975 CN14.16@13150,10025
NetCN14_20: CN14.20 SB13.1 | length 1685.4
  BottomLayer w5: SB13.1@12168,9742 12225,9799 12225,9925 12325,10025 12875,10025 12980,9920 12980,9695 13010,9665 13180,9665 13215,9700 13215,9760 CN14.20@13150,9825
NetCN14_25: CN14.25 SB17.2 | length 988.8
  BottomLayer w5: SB17.2@12163,9700 12178,9685 12940,9685 13015.46,9609.54 13015.46,9559.54 CN14.25@13050,9525
NetCN14_27: CN14.27 SB16.2 | length 1078.4
  BottomLayer w5: SB16.2@12168,9643 12200,9675 12935.86,9675 13005.46,9605.39 13005.46,9469.54 CN14.27@13050,9425
NetCN14_28: CN14.28 SB18.1 | length 1254.2
  BottomLayer w5: SB18.1@12168,9592 12241,9665 12931.72,9665 12995.46,9601.25 12995.46,9414.54 13025,9385 13110,9385 CN14.28@13150,9425
NetCN15_14: CN15.14 R60.1 R230.1 | length 1050.2
  TopLayer w5: R60.1@12997.5,8125 12997.5,8102.5 13025,8075 13200,8075 13275,8000 13425,8000 13450,7975 13575,7975 13605,7945 13605,7665 v1(13575,7635)
  BottomLayer w5: R230.1@13575,7602.5 v1(13575,7635)
NetCN15_16: CN15.16 R74.1 R223.1 | length 714.3
  TopLayer w5: R74.1@13202.5,8025 13202.5,7997.5 13250,7950 v1(13425,7950) 13450,7925 CN15.16@13510,7925
  BottomLayer w5: v1(13425,7950) 13460,7985 13460,8135 13550,8225 R223.1@13572.5,8225
NetCN15_18: CN15.18 R83.1 | length 328.2
  TopLayer w5: R83.1@13202.5,7925 13250,7925 13275,7900 13425,7900 13450,7875 CN15.18@13510,7875
NetCN15_20: CN15.20 R85.1 | length 328.2
  TopLayer w5: R85.1@13202.5,7825 13250,7825 13275,7800 13425,7800 13450,7825 CN15.20@13510,7825
NetCN16_2: CN16.2 R61.2 U13.3 U13.4 | length 343.1
  TopLayer w5: CN16.2@9975,8148 10027,8148 10105.32,8069.69 U13.3@10206.3,8069.69 ; U13.4@10143.7,8069.69 R61.2@10143.7,8146.2 ; R61.2@10145.5,8148 R61.2@10147.5,8150
NetCN16_3: CN16.3 R75.2 R84.2 U13.1 U13.6 | length 1124.5
  TopLayer w5: CN16.3@9895,8148 9943,8100 10000,8100 10069.68,8030.31 U13.1@10206.3,8030.31 ; v1(10147.5,8000) U13.6@10147.5,8026.52 ; v1(10450,7750) R84.2@10497.5,7750
  TopLayer w8: CN16.3@9895,8148 9972,8225 R75.2@10147.5,8225
  BottomLayer w5: v1(10147.5,8000) 10200,8000 v1(10450,7750)
NetCN17_11: CN17.11 R228.1 R229.2 | length 197.5
  BottomLayer w5: R229.2@13627.5,7750 R228.1@13627.5,7825 CN17.11@13750,7825
NetCN17_17: CN17.17 R232.2 | length 122.5
  BottomLayer w5: R232.2@13627.5,7525 CN17.17@13750,7525
NetCN17_19: CN17.19 R234.2 | length 122.5
  BottomLayer w5: R234.2@13627.5,7425 CN17.19@13750,7425
NetCN18_1: CN18.1 U26.1 | length 481.6
  TopLayer w50: CN18.1@9920,6590 9920,6745 10032.5,6857.5 U26.1@10200,6857.5
NetCN18_3: C47.2 CN18.2 CN18.3 U20.2 U26.2 Z1.1 | length 1363.3
  TopLayer w50: CN18.2@9817.95,6433.15 9716.85,6433.15 9675.91,6474.1 9675.91,6829.05 9922.13,7075.28 C47.2@10172.56,7075.28 ; Z1.1@10100,7200 Z1.1@10100,7205 ; Z1.1@10125.2,7200 10125.2,7012.3 10145,6992.5 U26.2@10175,6992.5
NetCN22_2: CN22.2 R130.2 U29.3 U29.4 | length 425.5
  TopLayer w5: CN22.2@9975,5998 9996.68,6019.69 U29.3@10206.3,6019.69 ; 10075,6019.69 10075,6120 10105,6150 R130.2@10147.5,6150
NetCN22_3: CN22.3 R128.2 R142.2 U29.1 U29.6 | length 734.5
  TopLayer w5: CN22.3@9895,5998 9943,5950 10000,5950 10030.32,5980.31 U29.1@10206.3,5980.31 ; R128.2@10125,6222.5 v1(10160,6222.5) ; R142.2@10143.7,5903.8 U29.6@10143.7,5980.31
  BottomLayer w5: v1(10143.7,5950) 10160,5966.3 v1(10160,6222.5)
NetD2_1: D2.1 R211.1 | length 525.6
  TopLayer w5: R211.1@11075,9302.5 11092.5,9302.5 11110,9285 v1(11110,9195) ; D2.1@11275,8870 v1(11275,8900)
  BottomLayer w5: v1(11110,9195) 11225,9080 11225,8950 v1(11275,8900)
NetD3_1: D3.1 R50.1 TR1.1 U19.1 | length 1417.4
  TopLayer w5: U19.1@12262.01,7388.58 12191.42,7388.58 12160,7420 12160,7635 12200,7675 12250,7675 12330,7755 12330,8100 12427.5,8197.5 12427.5,8362.5 12445,8380 D3.1@12445,8575
NetD5_1: D5.1 R108.1 TR2.1 U19.2 | length 395.4
  TopLayer w5: TR2.1@12090,7187.5 12090,7310 12077.5,7322.5 R108.1@12077.5,7375 12105,7375 12130,7350 12210,7350 12228.9,7368.9 U19.2@12262.01,7368.9
NetJP1_1: JP1.1 R179.2 | length 159.3
  BottomLayer w12: JP1.1@12725,11150 12747.5,11127.5 R179.2@12747.5,11000
NetJP3_3: JP3.3 R8.1 | length 132.1
  TopLayer w5: JP3.3@10900,10450 10977.5,10372.5 R8.1@10977.5,10350
NetJP4_1: CN2.15 JP4.1 R185.1 R189.2 R220.1 R221.1 R222.1 SB1.2 | length 6453.2
  TopLayer w5: JP4.1@10700,9975 10755,10030 11295,10030 11320,10005 v1(11355,10005) ; v1(12130,11510) 12130,11485 12148.43,11466.57 CN2.15@12148.43,11410
  BottomLayer w5: JP4.1@10700,9975 10700,10050 10725,10075 R185.1@10725,10122.5 10747.5,10122.5 10760,10135 10760,10165 10772.5,10177.5 R189.2@10800,10177.5 10800,10225 10750,10275 10750,10475 10725,10500 10600,10500 10555,10545 10555,11060 10660,11165 11015,11165 11225,11375 SB1.2@11225,11387 ; SB1.2@11218,11382 11180,11420 11180,11530 11200,11550 11950,11550 11990,11510 v1(12130,11510) ; v1(11355,10005) 11355,9935 11405,9885 11405,9400 11460,9345 11625,9345 11748,9222 11748,8768.42 12061.42,8455 12270,8455 12277.5,8447.5 R220.1@12277.5,8425 R222.1@12372.5,8425 R221.1@12372.5,8325
NetJP4_3: JP4.3 R186.2 R195.2 | length 232.9
  BottomLayer w5: JP4.3@10900,9975 10875,10000 R186.2@10875,10122.5 R195.2@10950,10122.5
NetJP5_1: CN2.16 JP5.1 R190.1 R192.2 R213.1 R217.1 R218.1 SB2.2 | length 6791.5
  TopLayer w5: v1(11065,9965) 11310,9965 11366.39,9908.61 v1(11406.39,9908.61) ; v1(12150,11490) 12168.11,11471.89 CN2.16@12168.11,11410
  BottomLayer w5: JP5.1@10700,9800 10800,9900 10950,9900 10975,9925 R192.2@11022.5,9925 11022.5,9947.5 11040,9965 v1(11065,9965) 11077.5,9977.5 R190.1@11077.5,10000 ; v1(11230,9965) 11230,10305 11005,10530 10629.85,10530 10585,10574.85 10585,11045.86 10674.14,11135 11060,11135 SB2.2@11300,11375 ; SB2.2@11307,11382 11335,11410 11335,11460 11415,11540 11935,11540 11985,11490 v1(12150,11490) ; v1(11406.39,9908.61) 11415,9900 11415,9410 11470,9355 11635,9355 11758,9232 11758,8772.56 12055.56,8475 12355,8475 12372.5,8492.5 12372.5,8552.5 12385,8565 12465,8565 12525,8625 R213.1@12572.5,8625 ; 12220,8475 12225,8480 12230,8475 ; 12225,8475 R217.1@12225,8522.5
NetJP5_3: JP5.3 R187.2 R191.2 | length 230.6
  BottomLayer w5: JP5.3@10900,9800 10925,9775 R187.2@11022.5,9775 11022.5,9795 R191.2@11077.5,9850
NetJP7_2: JP7.2 R210.1 | length 616.3
  TopLayer w5: JP7.2@10800,9450 10865,9515 v1(11150,9515) ; R210.1@11175,9302.5 11175,9370 v1(11195,9390)
  BottomLayer w5: v1(11150,9515) 11150,9435 v1(11195,9390)
NetJP8_1: D1.2 JP8.1 | length 118.6
  TopLayer w5: JP8.1@11175,9025 11220,8980 D1.2@11275,8980
NetJP8_2: JP7.3 JP8.2 | length 489.2
  BottomLayer w5: JP7.3@10900,9450 10900,9180 JP8.2@11055,9025
NetJP9_1: D2.2 JP9.1 | length 155.4
  TopLayer w5: JP9.1@11175,8850 11250,8850 11275,8825 D2.2@11275,8780
NetJP11_2: JP11.2 U9.6 | length 1682.6
  TopLayer w12: U9.6@11587.2,9345.87 11587.2,9287.8 v1(11600,9275)
  VCC w10: JP11.2@11150,7950 11115,7950 11060,8005 11060,8535 11125,8600 11125,8705 11600,9180 v1(11600,9275)
NetJP12_2: JP12.2 R55.2 | length 318.1
  TopLayer w30: JP12.2@11325,7950 11405,8030 11405,8100 11375,8130 R55.2@11375,8222.5
NetJP18_3: JP18.3 R121.1 | length 153.6
  TopLayer w12: R121.1@12327.5,9425 12375,9425 JP18.3@12450,9500
NetL4_2: C67.1 C68.1 CN20.13 CN20.14 L4.2 | length 3595.7
  TopLayer w5: C67.1@13090,6350 C67.1@13100,6350
  TopLayer w20: v1(10645,6760) 10645,6797.5 L4.2@10647.5,6800 ; C67.1@13100,6355 13145,6355 13172.44,6327.56 13297.44,6327.56 CN20.13@13375,6250 CN20.14@13475,6250
  BottomLayer w20: v1(10645,6760) 10645,6615 10965,6295 13330,6295 CN20.13@13375,6250 CN20.14@13475,6250
NetL5_2: C67.2 C68.2 CN20.15 CN20.16 L5.2 | length 3277.3
  TopLayer w15: v1(10800,6410) L5.2@10800,6447.5
  TopLayer w20: C67.2@13080,6250 13150,6250 13175,6275 13250,6275 CN20.15@13375,6150 CN20.16@13475,6150
  BottomLayer w20: v1(10800,6410) 10950,6260 13265,6260 CN20.15@13375,6150 CN20.16@13475,6150
NetLD1_2: LD1.2 R147.2 | length 383.6
  TopLayer w5: R147.2@11675,5872.5 11675,5850 11700,5825 11700,5725 11822.5,5602.5 LD1.2@11875,5602.5
NetLD2_2: LD2.2 R157.2 | length 177.5
  TopLayer w5: R157.2@11675,5722.5 11675,5675 11747.5,5602.5 LD2.2@11775,5602.5
NetLD3_2: LD3.2 R146.2 | length 311.4
  TopLayer w5: R146.2@11575,5872.5 11575,5850 11650,5775 11650,5675 11675,5650 LD3.2@11675,5602.5
NetLD4_2: LD4.2 R156.2 | length 120
  TopLayer w5: LD4.2@11575,5602.5 R156.2@11575,5722.5
NetLD6_2: LD6.2 R154.1 | length 517.5
  TopLayer w5: R154.1@10800,5722.5 10800,5550 10975,5375 LD6.2@10975,5277.5
NetLD7_2: LD7.2 R143.2 | length 715.1
  TopLayer w5: LD7.2@9884.06,5529.53 10129.53,5529.53 10350,5750 10350,5850 10375,5875 R143.2@10397.5,5875
NetLD7_3: LD7.3 R149.2 | length 641
  TopLayer w5: LD7.3@9884.06,5470.47 10095.47,5470.47 10397.5,5772.5 R149.2@10397.5,5775
NetLD7_4: LD7.4 R153.1 | length 753.9
  TopLayer w5: LD7.4@9765.94,5470.47 9804.53,5470.47 9850,5425 10075,5425 10325,5675 R153.1@10397.5,5675
NetLD9_1: LD9.1 R206.2 | length 151.1
  TopLayer w5: v1(12375,9250) 12425,9200 LD9.1@12425,9177.5
  BottomLayer w5: R206.2@12327.5,9275 12350,9275 v1(12375,9250)
NetLD9_2: LD9.2 T3.3 | length 140
  TopLayer w5: T3.3@12340,9199.5 12340,9160 12377.5,9122.5 LD9.2@12425,9122.5
NetR4_2: C91.1 R4.2 R177.2 U2.3 | length 442.9
  TopLayer w8: 13133.12,10925 R4.2@13172.5,10925
  TopLayer w12: v1(12910,10890) 12912.2,10887.8 13087.8,10887.8 13125,10925 13133.12,10925
  BottomLayer w12: R177.2@12802.5,10925 12835,10925 12870,10890 12945,10890 C91.1@12950,10895
NetR6_2: C98.2 R6.2 R179.1 R184.1 U3.2 | length 979.8
  TopLayer w12: v1(12715,10325) 12738.82,10348.82 12828.82,10348.82 12850,10370 12850,10525 12827.5,10547.5 v1@12827.5,10697.5
  BottomLayer w5: v1(12825,10700) v1@12827.5,10702.5
  BottomLayer w12: v1(12715,10325) 12700,10310 C98.2@12700,10252.5 R184.1@12775,10252.5 ; R179.1@12802.5,11000 12802.5,10977.5 12775,10950 12775,10750 v1(12825,10700)
NetR7_2: JP2.1 R7.2 | length 122.5
  TopLayer w5: R7.2@10150,10452.5 JP2.1@10150,10575
NetR9_2: CN5.9 R9.2 | length 350.5
  TopLayer w5: CN5.9@9799.5,10252.5 R9.2@10150,10252.5
NetR10_2: R10.2 U4.4 | length 110
  TopLayer w5: R10.2@10702.5,10125 U4.4@10812.5,10125
NetR15_2: R15.2 R18.2 U3.3 | length 294
  TopLayer w12: R15.2@12775,10252.5 R18.2@12675,10252.5 12675,10325 12724.41,10374.41 U3.3@12775.98,10374.41
NetR16_2: C5.1 R14.2 R16.2 | length 192.5
  TopLayer w12: C5.1@12375,10345 R14.2@12375,10252.5 R16.2@12475,10252.5
NetR17_2: C96.1 R17.2 R181.2 | length 248.4
  TopLayer w12: v1(12427.5,10315) 12465,10315 12527.5,10252.5 R17.2@12575,10252.5
  BottomLayer w5: C96.1@12427.5,10275 R181.2@12427.5,10350
NetR19_2: CN5.5 R19.2 | length 327.2
  TopLayer w5: CN5.5@9900,10207 10018,10207 10150,10075 R19.2@10150,10052.5
NetR20_2: C91.2 R20.2 R178.2 U2.2 | length 414.3
  TopLayer w12: v1(12910,10860) 12912.2,10862.2 13112.8,10862.2 13125,10850 R20.2@13172.5,10850
  BottomLayer w12: R178.2@12802.5,10850 12860.31,10850 12870.31,10860 12930,10860 C91.2@12940,10850
NetR26_1: R26.1 U7.3 | length 119.1
  TopLayer w12: R26.1@12550,9327.5 12550,9395 12571.85,9416.85 U7.3@12571.85,9437.6
NetR27_2: R27.2 R44.1 | length 102.5
  TopLayer w12: R44.1@12747.5,9272.5 R27.2@12850,9272.5
NetR28_1: CN7.2 R28.1 R35.1 | length 167.7
  TopLayer w5: R35.1@13325,9202.5 13325,9285 13355,9285 13363.62,9276.38 CN7.2@13406.65,9276.38
NetR29_1: R29.1 R31.1 R93.1 | length 150
  BottomLayer w5: R93.1@11472.5,9575 R31.1@11472.5,9725
NetR30_2: R25.2 R30.2 | length 105.2
  TopLayer w12: R30.2@12550,9110 12595,9110 12607.5,9122.5 R25.2@12650,9122.5
NetR41_2: R26.2 R41.2 U7.4 | length 244.5
  TopLayer w12: R26.2@12550,9272.5 12572.5,9272.5 12627.5,9327.5 R41.2@12650,9327.5 12650,9375 12678.15,9403.15 U7.4@12678.15,9437.6
NetR42_2: CN10.2 R42.2 | length 253.6
  TopLayer w5: R42.2@12575,8947.5 12575,8900 12550,8875 12550,8775 CN10.2@12600,8725
NetR44_2: C113.2 C114.1 R41.1 R44.2 R209.1 U8.1 | length 575.2
  TopLayer w12: R41.1@12650,9272.5 12672.5,9272.5 12727.5,9327.5 R44.2@12750,9327.5 12750,9375 12725,9400 12725,9495 12742.4,9512.4 U8.1@12771.85,9512.4
  BottomLayer w5: R209.1@12625,9277.5 R209.1@12625.06,9277.44 ; 12670,9277.44 12680,9287.44 12690,9277.44 ; 12695,9277.44 12695,9280
  BottomLayer w12: R209.1@12625.06,9277.44 C113.2@12724.72,9277.44 12724.65,9277.5 12722.5,9277.5 C113.2@12722.56,9277.44 ; v1(12680,9277.44) C114.1@12680,9365
NetR45_2: CN11.2 R45.2 | length 263.9
  TopLayer w5: CN11.2@12775,8725 12725,8775 12725,8850 12775,8900 R45.2@12775,8947.5
NetR48_2: R48.2 U12.1 | length 124.9
  TopLayer w5: R48.2@13652.5,8650 13700,8650 13705.91,8644.09 U12.1@13775,8644.09
NetR49_2: C27.1 C28.1 R49.2 U12.6 | length 485.4
  TopLayer w5: C28.1@13450,8705 13450,8745 13465,8760 13650,8760 ; R49.2@13650,8727.5 13650,8825 13656.1,8831.1 U12.6@13775,8831.1 ; 13650,8755 13645,8760 13650,8765
NetR52_2: R52.2 R54.2 RV3.2 | length 3463.2
  TopLayer w5: v1(10925,7750) 10925,7975 11075,8125 11125,8125 11175,8175 R54.2@11175,8222.5
  TopLayer w12: R54.2@11175,8222.5 R52.2@11275,8222.5
  BottomLayer w5: RV3.2@10645,5220 10645,5375 10510,5510 10510,6725 10925,7140 v1(10925,7750)
NetR53_1: LD8.1 R53.1 | length 100
  TopLayer w5: LD8.1@10975,8277.5 R53.1@11075,8277.5
NetR56_1: JP13.3 R56.1 R57.1 | length 499.2
  TopLayer w30: R56.1@11475,8222.5 11497.5,8222.5 11552.5,8277.5 11602.5,8277.5 11630,8250 11630,8195 11775,8050 JP13.3@11825,8050
NetR58_2: D4.2 JP13.2 JP16.2 L1.1 R58.2 | length 911.5
  TopLayer w12: 11920,7920 11890,7950 11925,7985
  TopLayer w30: R58.2@11675,8222.5 11732.5,8222.5 11750,8205 11807.5,8205 11825,8222.5 11902.5,8222.5 11925,8200 11925,7900 11975,7850 JP16.2@12050,7850 ; JP13.2@11825,7950 11925,7950
NetR63_2: R59.1 R62.1 R63.2 | length 338.9
  TopLayer w5: 12752.5,8252.5 R63.2@12775,8275
  TopLayer w12: R59.1@12500,8197.5 12697.5,8197.5 R63.2@12775,8275
NetR67_1: C84.2 R67.1 U34.3 | length 3727.2
  TopLayer w5: C84.2@12000,5777.72 C84.2@12000.28,5777.44 ; R67.1@12375,7972.5 12375,7950 12350,7925 12350,7775 12425,7700 12580,7700 12720,7560 12720,6639.43 12000.28,5919.72 C84.2@12000.28,5777.44 ; U34.3@12602.67,5174.73 12599.73,5174.73 12570,5145 12490,5145 12050,5585 12050,5760 12032.56,5777.44 C84.2@12000.28,5777.44
NetR68_1: C86.2 R68.1 U34.1 | length 3377.3
  TopLayer w5: C86.2@12200,5777.72 C86.2@12202.72,5775 ; C86.2@12200.28,5777.44 12200.28,6025.28 12740,6565 12740,7580 12600,7720 12480,7720 12425,7775 12425,7925 12450,7950 R68.1@12450,7972.5 ; C86.2@12210.01,5777.44 12222.56,5777.44 12250,5750 12250,5435 12465,5220 12492.05,5220 U34.1@12524.73,5252.67
NetR69_1: C88.2 R69.1 U34.6 | length 3025.5
  TopLayer w5: C88.2@12402.72,5775 C88.2@12400.28,5777.44 ; R69.1@12525,7972.5 12525,7900 12500,7875 12500,7760 12520,7740 12620,7740 12760,7600 12760,6485 12400.28,6125.28 C88.2@12400.28,5777.44 ; U34.6@12685,5410 12680,5410 12450,5640 12450,5750 12422.56,5777.44 C88.2@12400.28,5777.44
NetR70_2: R70.2 R80.2 U9.51 | length 218.1
  TopLayer w8: v1(11902.5,9872.5) 11927.5,9872.5 11961.22,9906.22 U9.51@11961.22,9954.13
  BottomLayer w8: R80.2@11875,9802.5 R70.2@11875,9872.5 v1(11902.5,9872.5)
NetR71_1: R71.1 U21.5 | length 1222.1
  TopLayer w5: R71.1@12750,7972.5 12775,7972.5 12825,7922.5 12825,7635 12882.5,7577.5 12882.5,7067.5 12900,7050 13025,7050 13050,7075 U21.5@13050,7137.5
NetR73_1: R73.1 R82.1 R95.1 | length 150
  BottomLayer w5: R73.1@11652.5,9450 R82.1@11652.5,9600
NetR74_2: R72.1 R74.2 | length 95
  TopLayer w5: R72.1@13052.5,8025 R74.2@13147.5,8025
NetR79_1: R79.1 R103.2 U19.32 | length 476.7
  TopLayer w5: U19.32@12443.9,7412.99 12443.9,7468.9 v1(12497.5,7522.5) R103.2@12525,7522.5 ; v1(12600,7770) R79.1@12600,7797.5
  BottomLayer w5: v1(12497.5,7522.5) 12600,7625 v1(12600,7770)
NetR81_1: R81.1 U21.2 | length 1190
  TopLayer w5: R81.1@12675,7972.5 12702.5,7972.5 12780,7895 12780,7640 12860,7560 12860,7040 12950,6950 U21.2@12950,6912.5
NetR82_2: C123.2 R82.2 | length 75
  BottomLayer w5: R82.2@11597.5,9600 C123.2@11597.5,9675
NetR86_2: R66.1 R86.2 T4.3 T5.2 | length 375.9
  TopLayer w5: R86.2@10377.5,7750 T4.3@10377.5,7897.5 ; T4.3@10390,7899.5 10424.5,7899.5 10462.5,7937.5 T5.2@10485,7937.5 10485,7975 10497.5,7987.5 R66.1@10497.5,8050
NetR89_1: C85.2 R89.1 U34.2 | length 3383.7
  TopLayer w5: R89.1@12377.5,7797.5 R89.1@12375,7797.5 12375,7775 12440,7710 12590,7710 12730,7570 12730,6605 12100.28,5975.28 C85.2@12100.28,5777.44 12122.56,5777.44 12150,5750 12150,5510 12480,5180 12530,5180 U34.2@12563.7,5213.7
NetR91_1: C87.2 R91.1 U34.4 | length 3103
  TopLayer w5: R91.1@12450,7797.5 12450,7775 12495,7730 12610,7730 12750,7590 12750,6525 12300.28,6075.28 C87.2@12300.28,5777.44 12322.56,5777.44 12350,5750 12350,5700 12730,5320 12747.95,5320 U34.4@12775.27,5347.33
NetR94_2: R92.2 R94.2 | length 167.2
  TopLayer w5: R92.2@12600,7972.5 12627.5,7972.5 12675,7925 R94.2@12675,7852.5
NetR96_1: R96.1 R117.2 U21.1 | length 1067.5
  TopLayer w5: R96.1@12750,7797.5 12750,7650 12850,7550 12850,7025 12900,6975 12900,6855 12925,6830 R117.2@12925,6802.5
NetR97_1: C36.1 R97.1 U16.1 | length 176.2
  TopLayer w12: C36.1@11250.35,7622.5 R97.1@11350,7622.5 11350,7595 11337.4,7582.4 U16.1@11337.4,7551.18
NetR100_1: C38.1 R100.1 U17.1 | length 174
  TopLayer w12: R100.1@11750,7622.5 11750.06,7622.44 C38.1@11825.28,7622.44 ; 11785,7622.44 11787.4,7620.04 U17.1@11787.4,7551.18 11787.4,7577.6
NetR107_1: C35.1 R106.2 R107.1 U16.5 | length 336
  TopLayer w5: 11177.5,7415 11187.5,7425 11177.5,7435
  TopLayer w12: C35.1@11177.5,7375 R106.2@11177.5,7475 ; 11177.5,7425 11300,7425 ; U16.5@11300,7448.82 11300,7425 ; R107.1@11327.5,7375 11327.5,7397.5 11300,7425
NetR109_1: C33.1 R109.1 | length 100
  TopLayer w8: R109.1@12652.5,7300 C33.1@12652.5,7400
NetR111_1: C41.1 R111.1 R114.2 U17.5 | length 334.2
  TopLayer w5: C41.1@11625,7327.5 R111.1@11827.5,7327.5 ; R114.2@11725,7327.5 11725,7375 11750,7400 U17.5@11750,7448.82
NetR112_1: CN20.8 R112.1 TR3.3 | length 409.5
  TopLayer w5: TR3.3@13227.5,7027.5 R112.1@13227.5,7150 ; TR3.3@13240,7024.5 13349.5,7024.5 CN20.8@13475,7150
NetR113_2: R113.2 U22.1 | length 224.3
  TopLayer w5: R113.2@13652.5,7050 13700,7050 U22.1@13825,6925
NetR115_2: C55.1 R115.2 | length 70
  TopLayer w5: R115.2@12425,6877.5 C55.1@12425,6947.5
NetR116_2: C56.1 R116.2 | length 70
  TopLayer w5: R116.2@12525,6877.5 C56.1@12525,6947.5
NetR119_1: R119.1 SB28.1 | length 70.9
  TopLayer w5: R119.1@13325,6802.5 v1(13362.5,6802.5)
  BottomLayer w5: v1(13362.5,6802.5) 13382.5,6802.5 SB28.1@13392,6793
NetR120_1: CN1.19 R120.1 SB4.1 | length 1354.7
  TopLayer w5: CN1.19@11377.17,11410 11377.17,11577.17 v1(11390,11590)
  BottomLayer w5: v1(11390,11590) 12065,11590 12125,11650 12200,11650 12250,11600 SB4.1@12250,11570 ; SB4.1@12258,11568 12298.5,11527.5 R120.1@12475,11527.5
